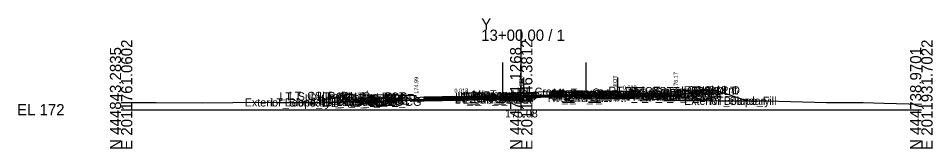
# Model space of a CAD drawing. Extents: x -26 to 3203, y -10 to 9532.
# Drawn here: x -25.7 to 202.8, y 6990.3 to 7022.8 of the extents above; entities that cross this region are included whole.
import ezdxf

# ---------------------------------------------------------------- set-up
doc = ezdxf.new("R2010")
doc.units = 0
for name, color, linetype in [('Default', 7, 'Continuous'), ('Exist Cross Section Cell', 7, 'Continuous'), ('Exist XS Center Line Elevation Label', 7, 'Continuous'), ('Exist XS Ground Line', 7, 'Continuous'), ('Prop CMT Conc Surface', 7, 'Continuous'), ('Prop CMT Concrete Structures', 7, 'Continuous'), ('Prop CMT Pvmt Course 1', 7, 'Continuous'), ('Prop CMT Pvmt Course 1 CG', 7, 'Continuous'), ('Prop CMT Pvmt Course 2', 7, 'Continuous'), ('Prop CMT Pvmt Course 3', 7, 'Continuous'), ('Prop CMT Pvmt Surface', 7, 'Continuous'), ('Prop CMT Slope Grass', 7, 'Continuous'), ('Prop CMT Subgrade Earthwork', 7, 'Continuous'), ('Prop Plan Preparation Sketches Hydraulic Ditch', 7, 'Continuous'), ('Prop XS Hydro Elevations', 7, 'Continuous'), ('Prop XS Label Text', 7, 'Continuous'), ('Prop XS SE Text', 7, 'Continuous'), ('Prop XS Side Slope Text', 7, 'Continuous'), ('Scratch_Level_0', 7, 'Continuous')]:
    doc.layers.add(name, color=color, linetype=linetype)

msp = doc.modelspace()

# ---------------------------------------------------------------- linework, layer by layer
at = {"layer": 'Exist Cross Section Cell'}
for p, q in [((100, 7000), (100, 7019.96)), ((0, 7000), (100, 7000)), ((100, 7000), (200, 7000))]:
    msp.add_line(p, q, dxfattribs=at)
at = {"layer": 'Exist XS Ground Line'}
msp.add_lwpolyline([(0, 7001.81), (8.73, 7001.8), (20.42, 7001.75), (27.9, 7001.84), (32.14, 7001.87), (38.81, 7001.79), (43.86, 7001.77), (47.08, 7001.81), (55.58, 7002.02), (66.25, 7002.2), (67.2, 7002.22), (80.28, 7002.56), (83.38, 7002.55), (89.35, 7002.52), (95.82, 7003.03), (97.59, 7003.16), (98.3, 7003.13), (99.36, 7003.1), (100, 7003.08), (100.54, 7003.06), (100.85, 7003.08), (101.35, 7003.09), (102.13, 7003.1), (103.64, 7003.14), (104.87, 7003.17), (106.9, 7003.22), (109.53, 7003.24), (110.33, 7003.25), (111.65, 7003.27), (112.25, 7003.28), (112.68, 7003.28), (113.76, 7003.26), (115.41, 7003.23), (115.79, 7003.22), (116.43, 7003.21), (118.32, 7003.19), (121.38, 7003.11), (121.77, 7003.09), (124.05, 7003.02), (124.88, 7003.04), (125.93, 7002.87), (133.17, 7002.6), (136.12, 7002.5), (139.65, 7002.34), (142.95, 7002.32), (149.36, 7002.25), (159.44, 7002.21), (161.08, 7002.2), (161.48, 7002.2), (164.34, 7002.13), (176.27, 7001.84), (177.71, 7001.84), (182.15, 7001.84), (185.45, 7001.81), (190.63, 7001.64), (200, 7001.38)], dxfattribs=at)
at = {"layer": 'Prop CMT Conc Surface'}
for points in [[(138.64, 7004.17), (138.64, 7004.67), (139.14, 7004.67)], [(73.76, 7002.99), (73.76, 7003.49), (73.26, 7003.49)], [(75.76, 7003.11), (73.76, 7002.99)], [(136.64, 7004.21), (138.64, 7004.17)]]:
    msp.add_lwpolyline(points, dxfattribs=at)
at = {"layer": 'Prop CMT Concrete Structures'}
for p, q in [((95.43, 7003.63), (95.42, 7003.46)), ((96.18, 7003.88), (95.43, 7003.63)), ((105.85, 7004.45), (96.18, 7003.88)), ((115.44, 7004.26), (105.85, 7004.45)), ((116.19, 7004.01), (115.44, 7004.26)), ((116.2, 7003.84), (116.19, 7004.01))]:
    msp.add_line(p, q, dxfattribs=at)
for points in [[(136.64, 7004.21), (138.64, 7004.17), (138.64, 7004.67), (139.14, 7004.67)], [(139.14, 7004.67), (139.14, 7003.67), (136.64, 7003.63)], [(75.76, 7003.11), (73.76, 7002.99), (73.76, 7003.49), (73.26, 7003.49)], [(73.26, 7003.49), (73.26, 7002.48), (75.76, 7002.52)], [(75.76, 7002.52), (75.76, 7003.11)], [(95.42, 7003.46), (116.2, 7003.84)], [(136.64, 7003.63), (136.64, 7004.21)]]:
    msp.add_lwpolyline(points, dxfattribs=at)
at = {"layer": 'Prop CMT Pvmt Course 1'}
for points in [[(94.17, 7003.44), (75.76, 7003.11)], [(75.76, 7002.86), (94.17, 7003.19)], [(75.76, 7003.11), (75.76, 7002.86)], [(94.17, 7003.44), (117.45, 7003.86)], [(117.45, 7003.61), (94.17, 7003.19)], [(94.17, 7003.19), (94.17, 7003.44)], [(94.17, 7003.19), (94.17, 7003.44)], [(117.45, 7003.86), (136.64, 7004.21)], [(136.64, 7003.96), (117.45, 7003.61)], [(117.45, 7003.86), (117.45, 7003.61)], [(117.45, 7003.61), (117.45, 7003.86)], [(136.64, 7004.21), (136.64, 7003.96)]]:
    msp.add_lwpolyline(points, dxfattribs=at)
for points in [[(94.17, 7003.19), (94.17, 7003.31), (94.17, 7003.31), (94.17, 7003.19)], [(117.45, 7003.61), (117.45, 7003.74), (117.45, 7003.74), (117.45, 7003.61)]]:
    msp.add_lwpolyline(points, close=True, dxfattribs=at)
at = {"layer": 'Prop CMT Pvmt Course 1 CG'}
for points in [[(75.76, 7002.52), (72.76, 7002.47), (72.42, 7002.13)], [(75.76, 7002.19), (75.76, 7002.52)], [(136.64, 7003.63), (139.64, 7003.68), (139.96, 7003.35)], [(136.64, 7003.29), (136.64, 7003.63)], [(139.96, 7003.35), (136.64, 7003.29)], [(72.42, 7002.13), (75.76, 7002.19)]]:
    msp.add_lwpolyline(points, dxfattribs=at)
at = {"layer": 'Prop CMT Pvmt Course 2'}
for points in [[(94.17, 7003.19), (75.76, 7002.86)], [(75.76, 7002.52), (94.17, 7002.86)], [(75.76, 7002.86), (75.76, 7002.52)], [(94.17, 7003.19), (117.45, 7003.61)], [(94.17, 7002.86), (94.17, 7003.19)], [(94.17, 7002.86), (94.17, 7003.19)], [(100.54, 7002.97), (94.17, 7002.86)], [(117.45, 7003.61), (136.64, 7003.96)], [(136.64, 7003.63), (124.05, 7003.4)], [(136.64, 7003.96), (136.64, 7003.63)]]:
    msp.add_lwpolyline(points, dxfattribs=at)
at = {"layer": 'Prop CMT Pvmt Course 3'}
for points in [[(94.17, 7002.86), (75.76, 7002.52)], [(75.76, 7002.52), (75.76, 7002.19)], [(75.76, 7002.19), (94.17, 7002.52)], [(94.17, 7002.86), (100.54, 7002.97)], [(94.17, 7002.52), (94.17, 7002.86)], [(94.17, 7002.52), (94.17, 7002.86)], [(100.54, 7002.64), (94.17, 7002.52)], [(124.05, 7003.4), (136.64, 7003.63)], [(136.64, 7003.29), (124.05, 7003.06)], [(136.64, 7003.63), (136.64, 7003.29)]]:
    msp.add_lwpolyline(points, dxfattribs=at)
at = {"layer": 'Prop CMT Pvmt Surface'}
for points in [[(94.17, 7003.44), (75.76, 7003.11)], [(94.17, 7003.44), (117.45, 7003.86)], [(117.45, 7003.86), (136.64, 7004.21)]]:
    msp.add_lwpolyline(points, dxfattribs=at)
at = {"layer": 'Prop CMT Slope Grass'}
for points in [[(139.14, 7004.67), (148.14, 7004.85)], [(148.14, 7004.85), (148.64, 7004.86), (156.54, 7002.22)], [(73.26, 7003.49), (63.76, 7003.68), (58.96, 7002.08)]]:
    msp.add_lwpolyline(points, dxfattribs=at)
at = {"layer": 'Prop CMT Subgrade Earthwork'}
for p, q in [((100.54, 7002.64), (100.54, 7003.06)), ((124.05, 7003.06), (124.05, 7003.02))]:
    msp.add_line(p, q, dxfattribs=at)
for points in [[(136.64, 7003.29), (139.96, 7003.35), (141.32, 7004.71)], [(75.76, 7002.19), (72.42, 7002.13), (71.02, 7003.53)], [(94.17, 7002.52), (75.76, 7002.19)], [(94.17, 7002.52), (100.54, 7002.64)], [(124.05, 7003.06), (136.64, 7003.29)]]:
    msp.add_lwpolyline(points, dxfattribs=at)
at = {"layer": 'Prop Plan Preparation Sketches Hydraulic Ditch'}
for p, q in [((95.42, 7003.46), (95.42, 7011.78)), ((116.2, 7003.84), (116.2, 7011.78))]:
    msp.add_line(p, q, dxfattribs=at)
at = {"layer": 'Prop XS Label Text'}
for p, q in [((100.54, 7008.06), (100.54, 7003.06)), ((124.05, 7008.02), (124.05, 7003.02))]:
    msp.add_line(p, q, dxfattribs=at)

# ---------------------------------------------------------------- texts
at = {"layer": 'Default'}
msp.add_text('-', height=0.0001, dxfattribs=at).set_placement((0, 7000))
at = {"layer": 'Exist Cross Section Cell'}
for s, p in [('Y', (90, 7019.96)), ('13+00.00 / 1', (90, 7017.16)), ('EL 172', (-26, 6998.6))]:
    msp.add_text(s, height=2.8, dxfattribs=at).set_placement(p)
for s, p in [('E 2011761.0602', (2.8, 6990)), ('E 2011846.3812', (102.8, 6990)), ('E 2011931.7022', (202.8, 6990)), ('N 444843.2835', (0, 6990)), ('N 444791.1268', (100, 6990)), ('N 444738.9701', (200, 6990))]:
    msp.add_text(s, height=2.8, rotation=90, dxfattribs=at).set_placement(p)
at = {"layer": 'Exist XS Center Line Elevation Label'}
msp.add_text('175.08', height=2, dxfattribs=at).set_placement((95.96, 6998.08))
msp.add_text('175.08', height=2, dxfattribs=at).set_placement((95.96, 6998.08))
at = {"layer": 'Prop XS Hydro Elevations'}
for s, p in [('176.17', (139.14, 7005.17)), ('174.99', (74.26, 7003.99))]:
    msp.add_text(s, height=1, rotation=90, dxfattribs=at).set_placement(p)
at = {"layer": 'Prop XS Label Text'}
for p in [(100.44, 7004.08), (123.95, 7004.05)]:
    msp.add_text('E. EOT', height=1, rotation=90, dxfattribs=at).set_placement(p)
at = {"layer": 'Prop XS SE Text'}
for p in [(83.32, 7004.24), (125.4, 7005.01)]:
    msp.add_text('0.018', height=1, rotation=1.0391, dxfattribs=at).set_placement(p)
at = {"layer": 'Prop XS Side Slope Text'}
for rotation, p in [(18.4349, (60.37, 7003.34)), (341.5651, (152.4, 7004.27))]:
    msp.add_text('3:1', height=1, rotation=rotation, dxfattribs=at).set_placement(p)
at = {"layer": 'Scratch_Level_0'}
for s, p in [('MI_Face In', (86.07, 7002.61)), ('MI_Top In', (87.78, 7002.86)), ('MI_Crown', (98.88, 7003.5)), ('RT_PV2_OEEOP', (106.71, 7002.61)), ('RT_PV1_OEEOP', (107.28, 7002.74)), ('RT_PV2_IEEOP', (107.35, 7002.61)), ('MI_Face Out', (107.71, 7003.03)), ('MI_Top Out', (107.92, 7003.28)), ('RT_PV1_IEEOP', (107.92, 7002.74)), ('RT_PV2_PGL1', (108.28, 7002.61)), ('RT_PV2_PGL', (108.61, 7002.61)), ('MI_Bot Out', (108.71, 7002.86)), ('RT_PV1_PGL', (109.18, 7002.86)), ('RT_Sub_Trench_Out_DLT', (121.84, 7003.71)), ('RT_CG_Top_Face', (125.85, 7003.67)), ('RT_CG1_Shelf_Out', (126.14, 7002.68)), ('RT_CG_Bot_IE', (126.5, 7002.63)), ('RT_PV2_OEOT', (126.76, 7002.96)), ('RT_PV3_OEOT', (126.76, 7002.63)), ('RT_CG_Top_Gut', (126.83, 7003.17)), ('RT_PV1_OEOT', (127.33, 7003.21)), ('RT_CG_Top_BOC', (127.37, 7003.67)), ('RT_CG_Bot_BOC', (127.41, 7002.67)), ('RT_Shld_O', (140.67, 7003.85)), ('CSLP_Pnt', (141.5, 7003.86)), ('Exterior Boundary', (30.92, 7000.81)), ('LT_Slope_Fill', (37.3, 7000.81)), ('LT_Sub_Trench_Out_DLT', (39.56, 7002.32)), ('LT_CSLP_Pnt', (41.91, 7002.46)), ('LT_CG1_Shelf_Out', (47.29, 7001.25)), ('LT_CG_Top_Face', (48.99, 7002.27)), ('LT_CG_Top_BOC', (49.52, 7002.27)), ('LT_CG_Bot_BOC', (49.55, 7001.26)), ('LT_CG_Top_Gut', (49.97, 7001.77)), ('LT_Sub_OEOP', (50.5, 7000.91)), ('LT_Sub_OEOT_CG', (51.1, 7000.97)), ('LT_CG_Bot_IE', (53.65, 7001.3)), ('LT_Sub_OEOT', (53.81, 7000.97)), ('LT_PV2_OEOT', (53.91, 7001.64)), ('LT_PV3_OEOT', (53.91, 7001.3)), ('LT_PV1_OEOT', (54.47, 7001.89)), ('LT_Sub_OEEOP', (83.38, 7001.52)), ('LT_PV2_OEEOP', (83.48, 7002.19)), ('LT_PV3_OEEOP', (83.48, 7001.86)), ('LT_PV1_OEEOP', (84.04, 7002.31)), ('LT_PV2_IEEOP', (84.12, 7002.19)), ('LT_PV1_IEEOP', (84.69, 7002.31)), ('LT_PV2_PGL1', (85.05, 7002.19)), ('LT_PV3_PGL1', (85.05, 7001.86)), ('LT_PV2_PGL', (85.38, 7002.19)), ('LT_PV4_PGL', (85.38, 7001.52)), ('LT_PV1_PGL', (85.95, 7002.44)), ('RT_Sub_OEEOP', (106.61, 7001.94)), ('RT_PV3_OEEOP', (106.71, 7002.28)), ('RT_PV3_PGL1', (108.28, 7002.28)), ('RT_PV4_PGL', (108.61, 7001.94)), ('RT_Sub_OEOT_CG', (123.96, 7002.29)), ('RT_Sub_OEOT', (126.67, 7002.29)), ('RT_Sub_OEOP', (130.03, 7002.35)), ('Exterior Boundary', (140.68, 7001.22)), ('RT_Slope_Fill', (147.01, 7001.22))]:
    msp.add_text(s, height=2, dxfattribs=at).set_placement(p)

doc.saveas('drawing.dxf')
